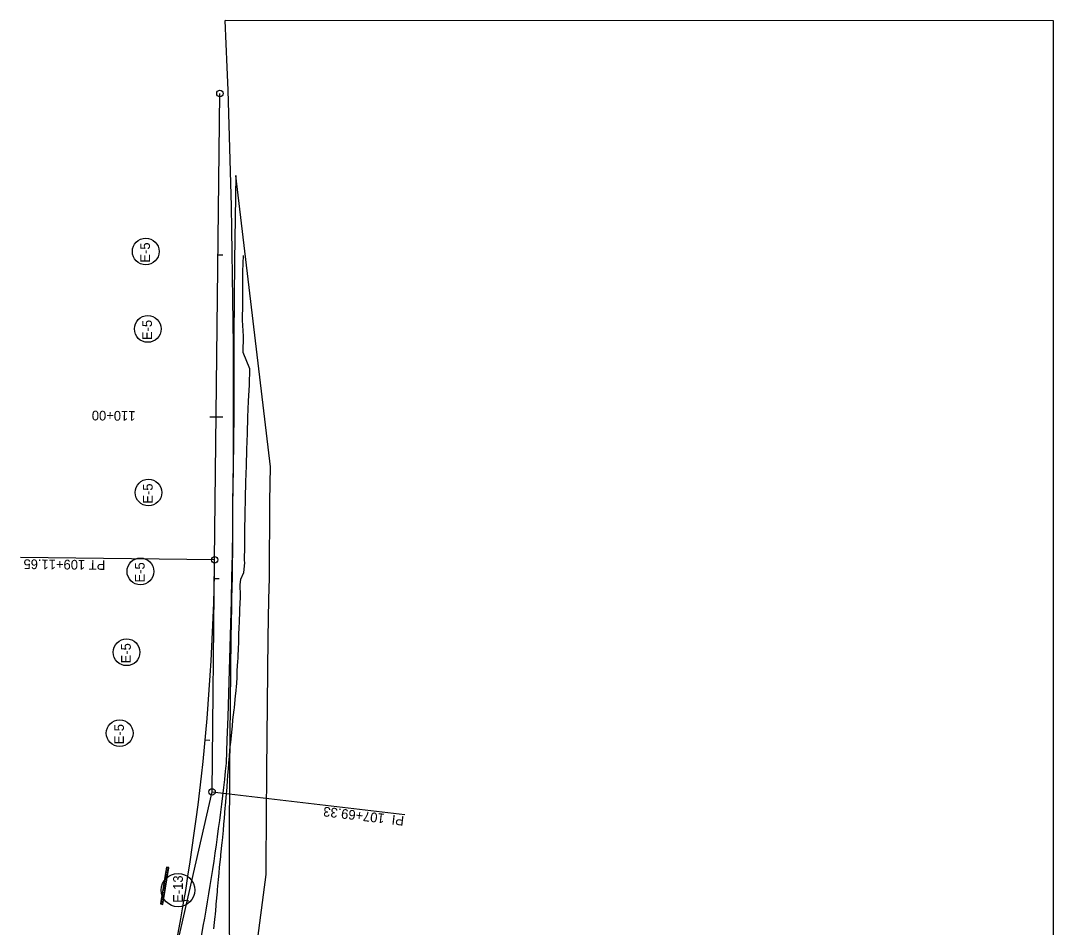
# Model space of a CAD drawing. Extents: x 1710760 to 1713003, y 548603 to 551142.
# Drawn here: x 1712364 to 1713003, y 550582 to 551142 of the extents above; entities that cross this region are included whole.
import ezdxf

# ---------------------------------------------------------------- set-up
doc = ezdxf.new("R2010")
doc.units = 0
for name, color, linetype in [('R_Erosion', 7, 'Continuous'), ('R_Erosion_STG 2', 7, 'Continuous'), ('R_Horz Alg', 7, 'Continuous'), ('R_Horz Alg Annot', 7, 'Continuous'), ('R_MOT', 7, 'Continuous'), ('R_No Plot', 7, 'Continuous'), ('R_Proposed Const Limits_Fill', 7, 'Continuous')]:
    doc.layers.add(name, color=color, linetype=linetype)

msp = doc.modelspace()

# ---------------------------------------------------------------- linework, layer by layer
at = {"layer": 'R_Erosion'}
for p, q in [((1712452.2, 550596.07), (1712455.88, 550618.77)), ((1712455.52, 550616.53), (1712454.28, 550618.25)), ((1712455.75, 550617.93), (1712455.04, 550618.91)), ((1712454.61, 550610.95), (1712453.37, 550612.67)), ((1712454.84, 550612.35), (1712453.6, 550614.07)), ((1712455.07, 550613.74), (1712453.83, 550615.46)), ((1712455.29, 550615.14), (1712454.05, 550616.86)), ((1712453.48, 550603.97), (1712452.24, 550605.69)), ((1712453.71, 550605.37), (1712452.47, 550607.09)), ((1712453.93, 550606.76), (1712452.69, 550608.48)), ((1712454.16, 550608.16), (1712452.92, 550609.88)), ((1712454.39, 550609.55), (1712453.15, 550611.27)), ((1712452.58, 550598.39), (1712451.34, 550600.11)), ((1712452.8, 550599.78), (1712451.56, 550601.5)), ((1712453.03, 550601.18), (1712451.79, 550602.9)), ((1712453.26, 550602.57), (1712452.02, 550604.29)), ((1712451.73, 550596.14), (1712450.88, 550597.31)), ((1712452.35, 550596.99), (1712451.11, 550598.71))]:
    msp.add_line(p, q, dxfattribs=at)
msp.add_lwpolyline([(1712455.88, 550618.77), (1712454.4, 550619.01), (1712450.72, 550596.31), (1712452.2, 550596.07)], dxfattribs=at)
for centre in [(1712441.55, 550999.63), (1712442.81, 550951.77), (1712443.24, 550850.64), (1712438.27, 550801.91), (1712429.71, 550751.91), (1712425.43, 550701.91)]:
    msp.add_circle(centre, 8.26, dxfattribs=at)
at = {"layer": 'R_Erosion_STG 2'}
msp.add_circle((1712461.52, 550604.93), 10.32, dxfattribs=at)
at = {"layer": 'R_Horz Alg'}
msp.add_line((1712484.19, 550809.05), (1712487.46, 551097.32), dxfattribs=at)
msp.add_arc((1711136.14, 550824.35), 1348.14, 347.20664, 359.34976, dxfattribs=at)
at = {"layer": 'R_Horz Alg Annot'}
for p, q in [((1712482.56, 550665.66), (1712484.19, 550809.05)), ((1712450.81, 550525.82), (1712482.56, 550665.66))]:
    msp.add_line(p, q, dxfattribs=at)
for points in [[(1712489.33, 550997.35), (1712486.33, 550997.39)], [(1712481.19, 550897.44), (1712489.19, 550897.35)], [(1712484.19, 550809.05), (1712364.2, 550810.41)], [(1712487.01, 550797.34), (1712484.01, 550797.4)], [(1712481.29, 550697.31), (1712478.3, 550697.59)], [(1712482.56, 550665.66), (1712601.74, 550651.62)], [(1712468.18, 550597.97), (1712465.22, 550598.47)]]:
    msp.add_lwpolyline(points, dxfattribs=at)
for centre in [(1712487.46, 551097.32), (1712484.19, 550809.05), (1712482.56, 550665.66)]:
    msp.add_circle(centre, 2, dxfattribs=at)
at = {"layer": 'R_MOT'}
for p, q in [((1712518.64, 550866.54), (1712497.28, 551046.54)), ((1712492.09, 550434.45), (1712516.1, 550614.45))]:
    msp.add_line(p, q, dxfattribs=at)
for points in [[(1712497.28, 551046.54), (1712496.4, 550994.08), (1712496.25, 550970.48), (1712496.11, 550946.87), (1712496.08, 550929.64), (1712496.05, 550912.4), (1712495.97, 550897.95), (1712495.9, 550883.5), (1712495.61, 550864.5), (1712495.32, 550845.5), (1712495.22, 550821.87), (1712495.11, 550798.25), (1712494.68, 550785.07), (1712494.59, 550779.89), (1712494.26, 550761.12), (1712494.05, 550740.6), (1712493.83, 550720.08), (1712493.62, 550699.57), (1712493.41, 550679.05), (1712493.32, 550664.55), (1712493.24, 550650.05), (1712493.16, 550635.55), (1712493.07, 550621.05), (1712493.15, 550603.63), (1712493.23, 550586.21), (1712493.31, 550568.79)], [(1712516.1, 550614.45), (1712516.07, 550621.04), (1712516.41, 550678.86), (1712517.26, 550760.8), (1712517.68, 550784.5), (1712518.11, 550797.83), (1712518.32, 550845.27), (1712518.64, 550866.54)]]:
    msp.add_lwpolyline(points, dxfattribs=at)
at = {"layer": 'R_No Plot'}
for p, q in [((1713002.92, 551142.32), (1712490.77, 551142.33)), ((1712491.46, 550683.43), (1712491.47, 550683.43))]:
    msp.add_line(p, q, dxfattribs=at)
msp.add_lwpolyline([(1712636.33, 549999.67), (1713002.92, 549999.67), (1713002.92, 551142.32)], dxfattribs=at)
for centre, radius, start, end in [((1706966.7, 550904.53), 5529.19, 357.70822, 2.46492), ((1711136.14, 550824.35), 1362.64, 347.20664, 354.06382)]:
    msp.add_arc(centre, radius, start, end, dxfattribs=at)
at = {"layer": 'R_Proposed Const Limits_Fill'}
msp.add_lwpolyline([(1712483.77, 550580.98), (1712484.15, 550584.95), (1712484.5, 550588.6), (1712484.62, 550589.9), (1712485.09, 550595.09), (1712485.19, 550596.23), (1712485.91, 550603.84), (1712486.03, 550605.22), (1712486.58, 550611.46), (1712486.92, 550615.35), (1712487.27, 550619.07), (1712487.91, 550625.45), (1712488.03, 550626.66), (1712488.79, 550634.25), (1712488.94, 550635.54), (1712489.58, 550641.83), (1712489.91, 550645.63), (1712490.24, 550649.42), (1712490.77, 550655.73), (1712490.87, 550657.02), (1712491.53, 550664.61), (1712491.62, 550665.83), (1712492.12, 550672.2), (1712492.4, 550675.93), (1712492.71, 550679.79), (1712493.19, 550686.02), (1712493.3, 550687.38), (1712493.66, 550691.51), (1712494.05, 550694.95), (1712494.18, 550696.09), (1712494.8, 550702.52), (1712495.13, 550706.16), (1712495.51, 550710.09), (1712496.19, 550716.23), (1712496.4, 550717.66), (1712497.17, 550725.23), (1712497.27, 550726.3), (1712497.82, 550732.81), (1712498.11, 550736.39), (1712498.02, 550740.43), (1712498.57, 550746.5), (1712498.64, 550748.01), (1712499.02, 550755.62), (1712499.07, 550756.61), (1712499.18, 550763.23), (1712499.32, 550766.73), (1712499.49, 550770.83), (1712499.68, 550776.84), (1712499.7, 550778.44), (1712500.1, 550786.04), (1712500.13, 550786.96), (1712500.05, 550793.65), (1712500.33, 550797.08), (1712502.18, 550801.23), (1712502.76, 550807.17), (1712502.74, 550808.84), (1712502.76, 550817.19), (1712502.94, 550827.19), (1712503.16, 550837.19), (1712503.25, 550847.19), (1712503.56, 550857.18), (1712503.84, 550867.18), (1712504.13, 550877.18), (1712504.43, 550887.18), (1712504.72, 550897.17), (1712505.03, 550907.17), (1712505.65, 550917.16), (1712505.94, 550927.16), (1712501.72, 550937.21), (1712502.01, 550947.21), (1712501.48, 550957.21), (1712501.68, 550967.21), (1712501.67, 550977.21), (1712501.7, 550987.21), (1712502.03, 550997.21)], dxfattribs=at)

# ---------------------------------------------------------------- texts
at = {"layer": 'R_Erosion'}
for p in [(1712444.16, 550992.76), (1712445.42, 550944.89), (1712445.84, 550843.77), (1712440.87, 550795.04), (1712432.32, 550745.04), (1712428.04, 550695.04)]:
    msp.add_text('E-5 ', height=5.999, rotation=90, dxfattribs=at).set_placement(p)
at = {"layer": 'R_Erosion_STG 2'}
msp.add_text('E-13', height=5.999, rotation=90, dxfattribs=at).set_placement((1712464.52, 550597.02))
at = {"layer": 'R_Horz Alg Annot'}
for s, rotation, p in [('110+00', 179.34976, (1712435.23, 550900.96)), ('PT 109+11.65', 179.34976, (1712416.62, 550808.82)), ('PI  107+69.33', 173.2782, (1712601.62, 550650.62))]:
    msp.add_text(s, height=6, rotation=rotation, dxfattribs=at).set_placement(p)

doc.saveas('drawing.dxf')
